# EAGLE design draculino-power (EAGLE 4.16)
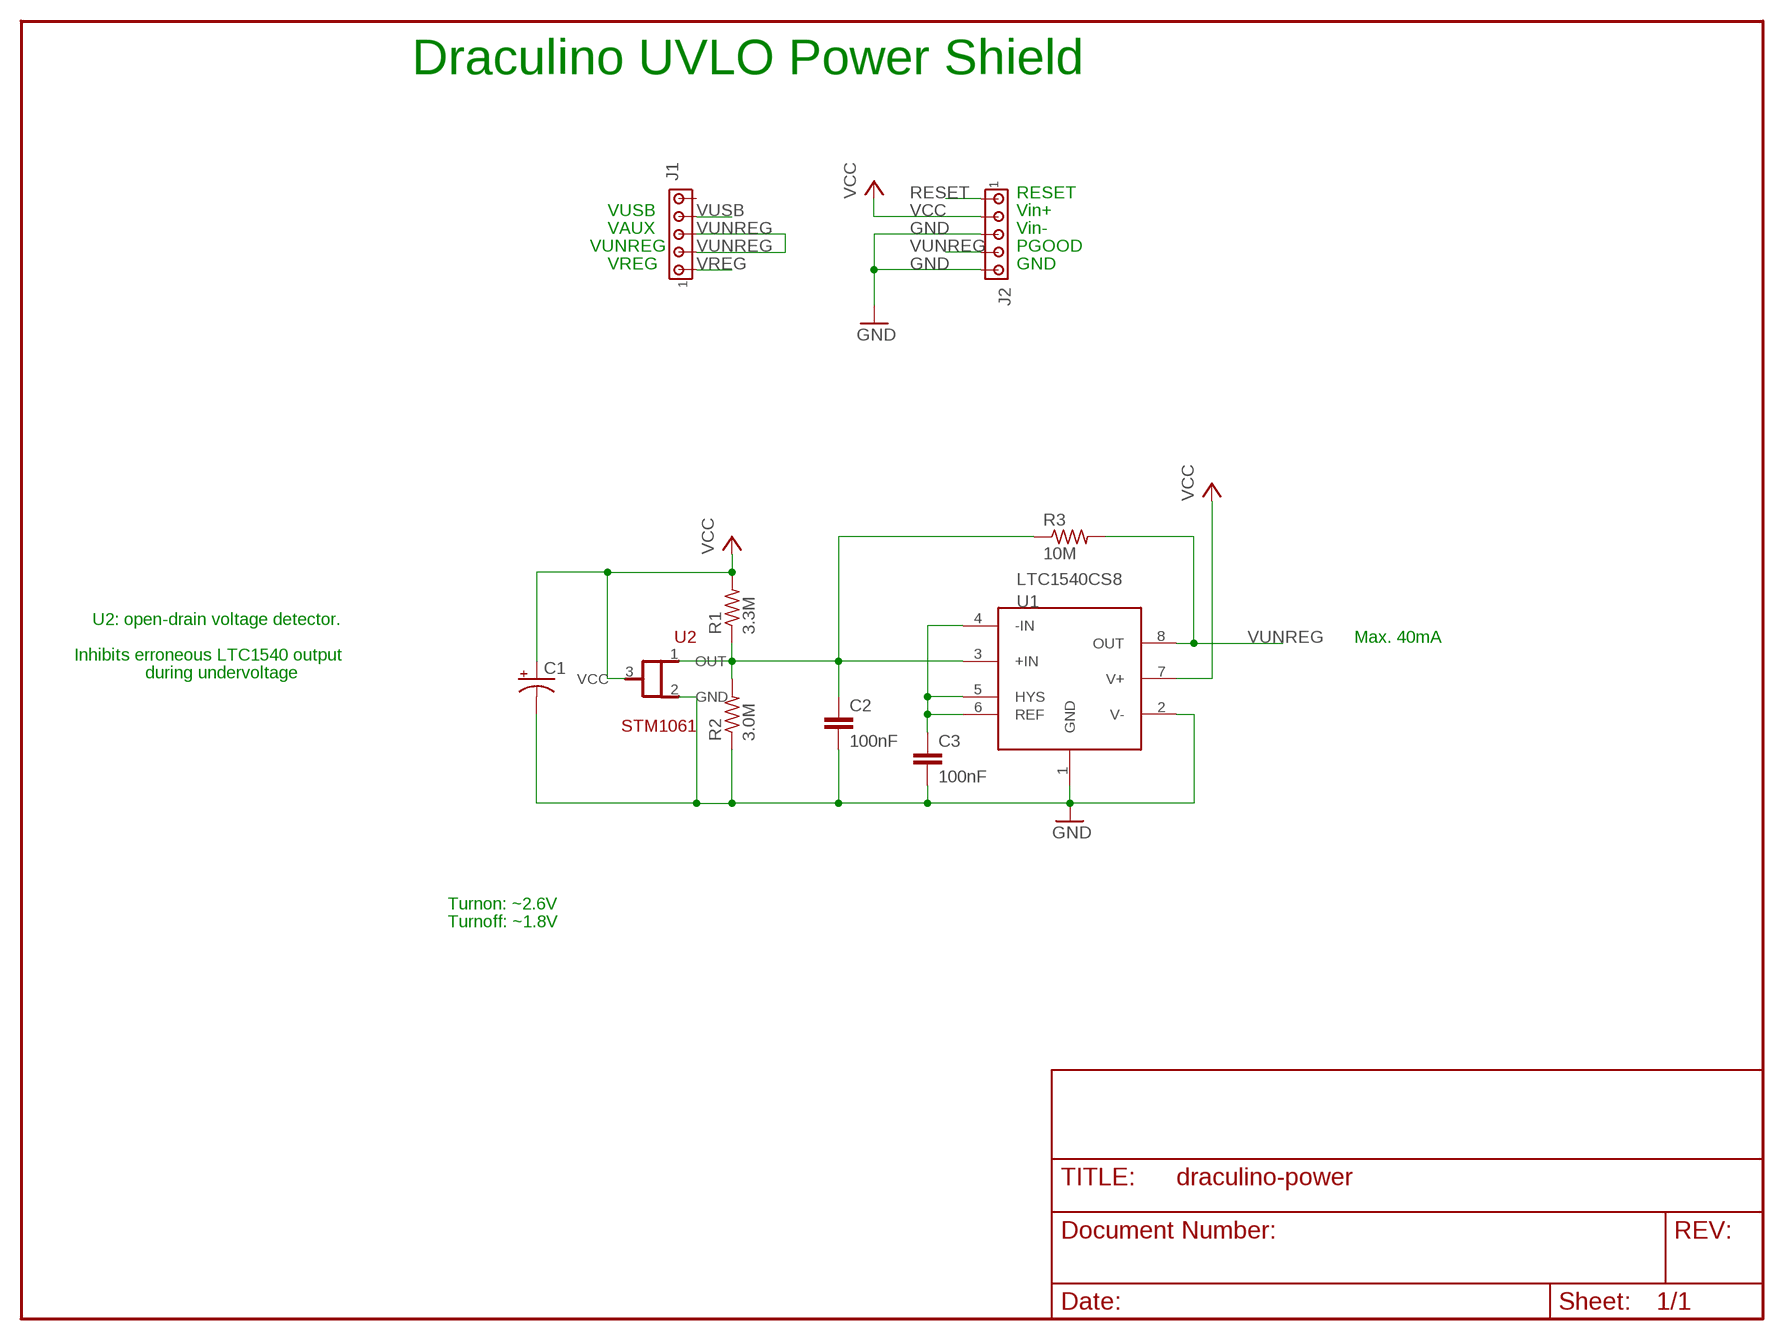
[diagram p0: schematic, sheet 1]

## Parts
C1  CPOL-USD  [PANASONIC_D]
C2  100nF  C-EUC0805  [C0805]
C3  100nF  C-EUC0805  [C0805]
J1  MTA05-100  [10X05MTA]
J2  MTA05-100  [10X05MTA]
R1  3.3M  R-US_R0805  [R0805]
R2  3.0M  R-US_R0805  [R0805]
R3  10M  R-US_R0805  [R0805]
U1  LTC1540CS8  LTC1540ACS8  [SO-8]
U2  STM1061  [SOT23]

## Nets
GND [pwr]: C1.- C2.2 C3.2 J2.3 J2.5 R2.1 U1.1(GND) U1.2(V-) U2.2(GND)
N$1: C3.1 U1.4(-IN) U1.5(HYS) U1.6(REF)
N$2: C2.1 R1.1 R2.2 R3.1 U1.3(+IN) U2.1(OUT)
RESET: J2.1
VCC [pwr]: C1.+ J2.2 R1.2 U1.7(V+) U2.3(VCC)
VREG: J1.1
VUNREG [pwr]: J1.2 J1.3 J2.4 R3.2 U1.8(OUT)
VUSB: J1.4
Unconnected: J1.5

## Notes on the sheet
- Draculino UVLO Power Shield
- RESET
- VUSB | Vin+
- VAUX | Vin-
- VUNREG | PGOOD
- VREG | GND
- U2: open-drain voltage detector.
- Max. 40mA
- Inhibits erroneous LTC1540 output
- during undervoltage
- Turnon: ~2.6V
- Turnoff: ~1.8V

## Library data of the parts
C1 = rcl:CPOL-US: POLARIZED CAPACITOR, American symbol
C2 C3 = rcl:C-EU: CAPACITOR, European symbol
J1 J2 = con-amp:MTA05-100: AMP connector
R1-R3 = rcl:R-US_: RESISTOR, American symbol
U1 = mideeval:LTC1540A: LTC1540A Comparator, Rectangular Symbol, S08 Package JR 9.18.03
U2 = mideeval:STM1061

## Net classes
1 pwr: width 0.305 mm, drill 0.203 mm, clearance 0.508 mm
4 digital: width 0.203 mm, drill 0.203 mm, clearance 0.381 mm

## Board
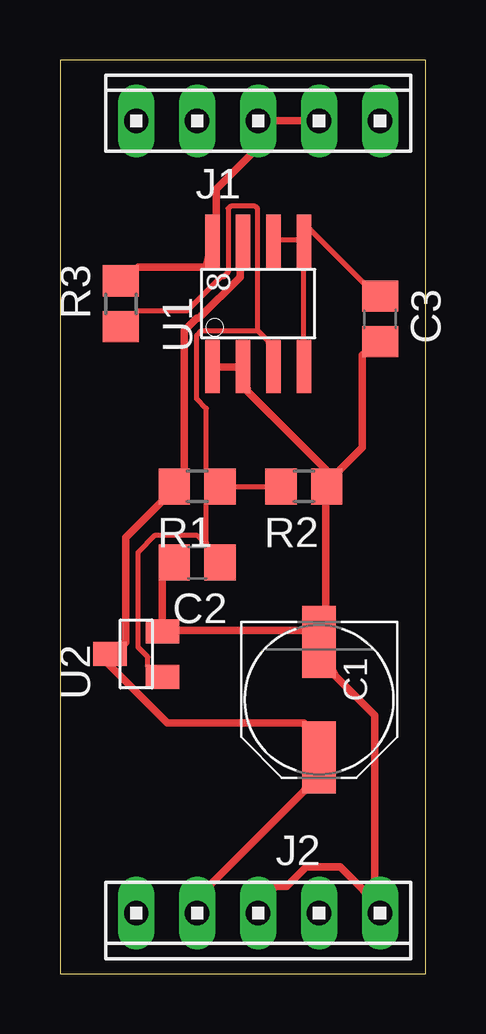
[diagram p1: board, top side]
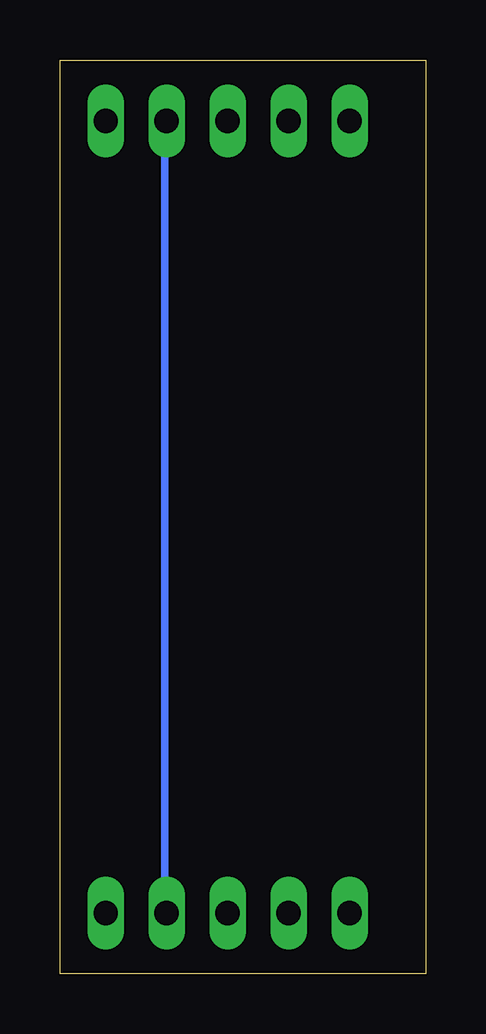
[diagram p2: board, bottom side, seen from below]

Size 15.24 x 38.1 mm. Coordinates in mm from the lower left corner, seen from the top.
Outline: 0,0 15.24,0 15.24,38.1 0,38.1 0,0
Copper layers (1*16): Top 0.035mm / dielectric 1.5mm / Bottom 0.035mm
Design rules "default": minimum track width 8mil, minimum drill 15mil, track to track 8mil, track to pad 8mil, pad to pad 8mil, via to via 8mil, smd to smd 8mil, copper to edge 40mil, drill to drill 8mil, minimum pad ring 10mil, minimum via ring 8mil, stop-mask expansion 4mil, vias tented up to drill 0mil, thermal gap 10mil

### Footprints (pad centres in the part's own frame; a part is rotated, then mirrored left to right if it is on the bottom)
PANASONIC_D = smd 3 x 1.4: + 2.4,0; - -2.4,0
C0805 = smd 1.3 x 1.5: 1 -0.95,0; 2 0.95,0
10X05MTA = drill 1.016 long: 1 5.08,0; 2 2.54,0; 3 0,0; 4 -2.54,0; 5 -5.08,0
R0805 = smd 1.3 x 1.5: 1 -0.95,0; 2 0.95,0
SO-8 = smd 0.61 x 2.21: 1 -1.905,-2.616; 2 -0.635,-2.616; 3 0.635,-2.616; 4 1.905,-2.616; 5 1.905,2.616; 6 0.635,2.616; 7 -0.635,2.616; 8 -1.905,2.616
SOT23 = smd 1 x 1.4: 1 -0.95,-1.1; 2 0.95,-1.1; 3 0,1.1

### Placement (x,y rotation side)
C1  10.79,11.43 270 top
C2  5.71,17.14 180 top
C3  13.34,27.3 270 top
J1  8.26,35.56 0 top
J2  8.26,2.54 180 top
R1  5.71,20.32 180 top
R2  10.16,20.32 180 top
R3  2.54,27.94 90 top
U1  8.26,27.94 0 top
U2  3.17,13.34 90 top

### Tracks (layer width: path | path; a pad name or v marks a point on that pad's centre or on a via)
GND
  Top 0.305: J2.3 8.94,3.66 9.45,3.66 10.26,4.47 11.68,4.47 12.6,3.56 J2.5 13.11,3.96 13.11,10.77 11.48,12.39 C1.- | U1.1 6.6,25.3 7.42,25.3 U1.2 7.82,24.28 11.07,21.03 R2.1 | C2.2 4.27,16.46 4.27,14.73 U2.2 4.88,14.33 10.16,14.33 C1.- | R2.1 11.07,19.61 11.07,15.24 C1.- | C3.2 12.6,25.81 12.6,21.95 11.68,21.03 R2.1
N$1
  Top 0.203: C3.1 12.6,28.85 10.36,31.09 U1.5 | U1.4 U1.5 | U1.6 9.14,30.58 9.96,30.58 U1.5
N$2
  Top 0.203: R1.1 R2.2 | 6.04,17.93 6.1,17.88 C2.1 | 6.04,17.93 5.69,18.29 3.96,18.29 3.25,17.58 3.25,13.61 3.66,13.21 3.66,12.8 U2.1 | R1.1 6.1,19.61 6.1,17.98 6.04,17.93 | 8.23,26.82 8.23,31.9 8.13,32 7.11,32 7.01,31.9 7.01,29.26 6.81,29.06 6.71,29.06 5.28,27.64 3.25,27.64 R3.1 | 8.23,26.82 8.64,26.42 U1.3 | 8.23,26.82 5.89,26.82 5.69,26.62 5.69,23.98 6.1,23.57 6.1,21.03 R1.1
VCC
  Top 0.305: J2.2 6.3,3.76 10.16,7.62 C1.+ 10.16,10.46 4.47,10.46 2.03,12.9 U2.3 2.74,13.82 2.74,18.19 4.17,19.61 R1.2 5.18,21.03 5.18,26.82 5.69,27.33 5.79,27.33 7.52,29.06 7.52,29.46 U1.7
VUNREG
  Top 0.305: R3.2 3.25,29.46 6.1,29.46 U1.8 6.5,31.6 6.5,32.72 7.92,34.14 J1.3 J1.2
  Bottom 0.305: J2.4 10.87,3.96 10.87,34.14 J1.2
